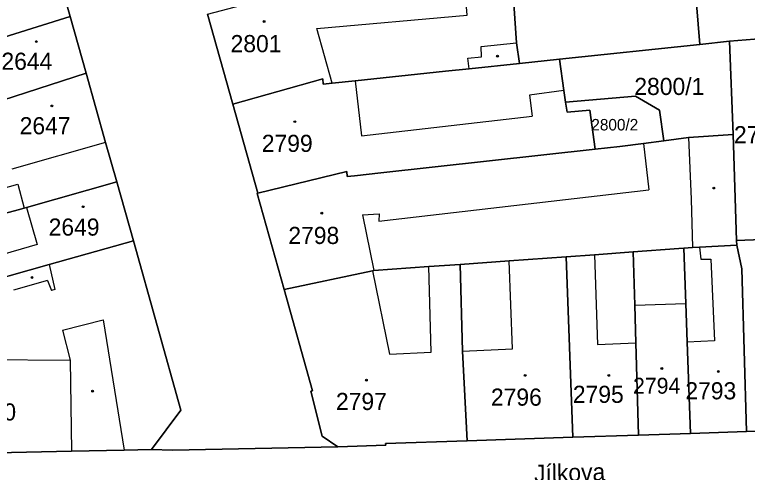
# Model space of a CAD drawing. Extents: x -596233 to -595156, y -1161235 to -1159375.
# Drawn here: x -595617.7 to -595544.9, y -1160883.5 to -1160838.1 of the extents above; entities that cross this region are included whole.
import ezdxf

# ---------------------------------------------------------------- set-up
doc = ezdxf.new("R2010")
doc.units = 0
for name, color, linetype in [('KN_CAR_KR', 7, 'Continuous'), ('KN_KULTURY', 7, 'Continuous'), ('KN_PARC_CIS_POZ', 7, 'Continuous'), ('KN_PARC_CIS_STAV', 7, 'Continuous'), ('KN_PARC_PLOCHA', 7, 'Continuous'), ('KN_ULICE', 7, 'Continuous'), ('parcely_l', 7, 'Continuous')]:
    doc.layers.add(name, color=color, linetype=linetype)

msp = doc.modelspace()

# ---------------------------------------------------------------- linework, layer by layer
at = {"layer": 'KN_CAR_KR'}
for points in [[(-595572.77, -1160838.12), (-595572.92, -1160836.45)], [(-595587.72, -1160839.46), (-595572.77, -1160838.12)], [(-595586.2, -1160844.88), (-595587.72, -1160839.46)], [(-595571.38, -1160841.24), (-595567.86, -1160840.88)], [(-595571.34, -1160842.27), (-595571.38, -1160841.24)], [(-595572.71, -1160842.42), (-595571.34, -1160842.27)], [(-595572.59, -1160843.45), (-595572.71, -1160842.42)], [(-595583.91, -1160844.64), (-595583.29, -1160850.11)], [(-595563.16, -1160845.63), (-595566.6, -1160846.09)], [(-595566.6, -1160846.09), (-595566.33, -1160848.16)], [(-595583.29, -1160850.11), (-595566.33, -1160848.16)], [(-595550.79, -1160850.29), (-595550.52, -1160856.41)], [(-595608.7, -1160850.76), (-595618.02, -1160853.42)], [(-595555.24, -1160850.87), (-595554.73, -1160855.47)], [(-595624.81, -1160856.96), (-595617.44, -1160854.91)], [(-595617.44, -1160854.91), (-595616.79, -1160857.29)], [(-595581.54, -1160858.57), (-595554.73, -1160855.47)], [(-595550.52, -1160856.41), (-595550.38, -1160861.19)], [(-595616.57, -1160857.22), (-595615.5, -1160860.91)], [(-595583.18, -1160857.96), (-595581.51, -1160857.87)], [(-595583.18, -1160857.96), (-595582.05, -1160863.48)], [(-595581.51, -1160857.87), (-595581.54, -1160858.57)], [(-595615.5, -1160860.91), (-595619.75, -1160862.14)], [(-595549.68, -1160861.15), (-595549.57, -1160862.36)], [(-595560.11, -1160861.92), (-595559.84, -1160870.83)], [(-595549.57, -1160862.36), (-595548.55, -1160862.34)], [(-595548.55, -1160862.34), (-595548.19, -1160870.45)], [(-595614.32, -1160862.9), (-595613.75, -1160865.37)], [(-595576.36, -1160871.58), (-595576.6, -1160863.09)], [(-595568.26, -1160871.25), (-595568.62, -1160862.52)], [(-595582.18, -1160863.51), (-595580.48, -1160871.77)], [(-595614.49, -1160864.47), (-595617.87, -1160865.43)], [(-595614.49, -1160864.47), (-595614.09, -1160865.47)], [(-595613.75, -1160865.37), (-595614.09, -1160865.47)], [(-595556.13, -1160866.93), (-595551.05, -1160866.76)], [(-595612.98, -1160869.39), (-595608.96, -1160868.37)], [(-595608.96, -1160868.37), (-595606.86, -1160881.31)], [(-595612.98, -1160869.39), (-595612.24, -1160872.38)], [(-595559.84, -1160870.83), (-595556.03, -1160870.66)], [(-595548.19, -1160870.45), (-595550.92, -1160870.59)], [(-595580.48, -1160871.77), (-595576.36, -1160871.58)], [(-595573.23, -1160871.48), (-595568.26, -1160871.25)], [(-595620.71, -1160872.33), (-595612.24, -1160872.38)], [(-595612.24, -1160872.38), (-595612.11, -1160881.42)]]:
    msp.add_lwpolyline(points, dxfattribs=at)
at = {"layer": 'KN_KULTURY'}
for centre, radius in [((-595592.96, -1160838.77), 0.09), ((-595592.96, -1160838.77), 0.0398), ((-595615.59, -1160840.76), 0.09), ((-595615.59, -1160840.76), 0.0398), ((-595569.77, -1160842.21), 0.09), ((-595569.77, -1160842.21), 0.0398), ((-595614.04, -1160847.15), 0.09), ((-595614.04, -1160847.15), 0.0398), ((-595589.9, -1160848.71), 0.09), ((-595589.9, -1160848.71), 0.0398), ((-595548.28, -1160855.3), 0.09), ((-595548.28, -1160855.3), 0.0398), ((-595610.93, -1160857.15), 0.09), ((-595610.93, -1160857.15), 0.0398), ((-595587.23, -1160857.79), 0.09), ((-595587.23, -1160857.79), 0.0398), ((-595616.02, -1160864.17), 0.09), ((-595616.02, -1160864.17), 0.0398), ((-595553.44, -1160873.21), 0.09), ((-595553.44, -1160873.21), 0.0398), ((-595567.02, -1160873.89), 0.09), ((-595567.02, -1160873.89), 0.0398), ((-595558.71, -1160873.89), 0.09), ((-595558.71, -1160873.89), 0.0398), ((-595547.82, -1160873.51), 0.09), ((-595547.82, -1160873.51), 0.0398), ((-595582.79, -1160874.37), 0.09), ((-595582.79, -1160874.37), 0.0398), ((-595610, -1160875.46), 0.09), ((-595610, -1160875.46), 0.0398)]:
    msp.add_circle(centre, radius, dxfattribs=at)
at = {"layer": 'KN_PARC_PLOCHA'}
for points in [[(-595516.7, -1160837.52), (-595520.65, -1160838.61), (-595532.3, -1160839.58), (-595534.35, -1160839.75), (-595540.07, -1160840.2), (-595546.72, -1160840.73), (-595549.67, -1160841.05), (-595550.5, -1160830.91), (-595521.89, -1160826.97), (-595520.91, -1160831.93), (-595518.32, -1160831.24)], [(-595549.67, -1160841.05), (-595563.61, -1160842.5), (-595567.57, -1160842.92), (-595567.86, -1160840.88), (-595568.41, -1160833.12), (-595562.92, -1160832.28), (-595552.81, -1160831.16), (-595550.5, -1160830.91)], [(-595612.24, -1160838.27), (-595623.79, -1160841.88), (-595624.03, -1160841.96), (-595629.09, -1160843.48), (-595629.71, -1160843.67), (-595630.92, -1160839.99), (-595631.49, -1160837.94), (-595629.38, -1160837.31), (-595625.46, -1160836.14), (-595613.83, -1160832.66)], [(-595567.57, -1160842.92), (-595572.59, -1160843.45), (-595574.94, -1160843.7), (-595583.91, -1160844.64), (-595586.2, -1160844.88), (-595587.08, -1160844.97), (-595587.13, -1160844.47), (-595596.07, -1160846.97), (-595598.59, -1160838.03), (-595589.75, -1160835.69), (-595589.61, -1160836.22), (-595588.64, -1160835.88), (-595578.3, -1160834.49), (-595577.15, -1160834.34), (-595571.41, -1160833.57), (-595571.18, -1160833.54), (-595570.01, -1160833.36), (-595568.41, -1160833.12), (-595567.86, -1160840.88)], [(-595610.65, -1160843.89), (-595623.77, -1160848.14), (-595625, -1160848.51), (-595625.85, -1160848.77), (-595627.17, -1160849.16), (-595627.36, -1160849.22), (-595630.55, -1160850.17), (-595631.95, -1160844.35), (-595629.71, -1160843.67), (-595629.09, -1160843.48), (-595624.03, -1160841.96), (-595623.79, -1160841.88), (-595612.24, -1160838.27)], [(-595539.53, -1160855.06), (-595539.31, -1160860.19), (-595543.5, -1160860.39), (-595546.01, -1160860.51), (-595546.35, -1160849.97), (-595546.72, -1160840.73), (-595540.07, -1160840.2)], [(-595546.35, -1160849.97), (-595550.79, -1160850.29), (-595553.23, -1160850.61), (-595553.67, -1160847.56), (-595556.04, -1160846.19), (-595562.99, -1160846.78), (-595563.16, -1160845.63), (-595563.61, -1160842.5), (-595549.67, -1160841.05), (-595546.72, -1160840.73)], [(-595562.99, -1160846.78), (-595562.85, -1160847.75), (-595560.58, -1160847.57), (-595560.05, -1160851.43), (-595581.35, -1160853.79), (-595583.98, -1160854.08), (-595584.69, -1160854.16), (-595584.74, -1160853.66), (-595593.57, -1160855.82), (-595596.07, -1160846.97), (-595587.13, -1160844.47), (-595587.08, -1160844.97), (-595586.2, -1160844.88), (-595583.91, -1160844.64), (-595574.94, -1160843.7), (-595572.59, -1160843.45), (-595567.57, -1160842.92), (-595563.61, -1160842.5), (-595563.16, -1160845.63)], [(-595607.59, -1160854.68), (-595616.57, -1160857.22), (-595616.79, -1160857.29), (-595617.4, -1160857.46), (-595621.64, -1160858.6), (-595624.18, -1160859.28), (-595624.81, -1160856.96), (-595625.16, -1160855.38), (-595623.41, -1160854.96), (-595624.58, -1160850.23), (-595626.66, -1160850.89), (-595627.17, -1160849.16), (-595625.85, -1160848.77), (-595625, -1160848.51), (-595623.77, -1160848.14), (-595610.65, -1160843.89), (-595608.7, -1160850.76)], [(-595553.23, -1160850.61), (-595555.24, -1160850.87), (-595557.62, -1160851.16), (-595560.05, -1160851.43), (-595560.58, -1160847.57), (-595562.85, -1160847.75), (-595562.99, -1160846.78), (-595556.04, -1160846.19), (-595553.67, -1160847.56)], [(-595546.01, -1160860.51), (-595545.99, -1160860.97), (-595549.68, -1160861.15), (-595550.38, -1160861.19), (-595551.24, -1160861.25), (-595551.74, -1160861.29), (-595556.27, -1160861.63), (-595560.11, -1160861.92), (-595562.95, -1160862.12), (-595568.62, -1160862.52), (-595573.47, -1160862.87), (-595576.6, -1160863.09), (-595582.05, -1160863.48), (-595582.18, -1160863.51), (-595590.97, -1160865.36), (-595593.63, -1160855.84), (-595593.57, -1160855.82), (-595584.74, -1160853.66), (-595584.69, -1160854.16), (-595583.98, -1160854.08), (-595581.35, -1160853.79), (-595560.05, -1160851.43), (-595557.62, -1160851.16), (-595555.24, -1160850.87), (-595553.23, -1160850.61), (-595550.79, -1160850.29), (-595546.35, -1160849.97)], [(-595605.93, -1160860.54), (-595614.32, -1160862.9), (-595618.29, -1160864.01), (-595619.24, -1160864.28), (-595621.46, -1160864.93), (-595622.55, -1160865.24), (-595623.13, -1160863.11), (-595623.49, -1160861.8), (-595624.18, -1160859.28), (-595621.64, -1160858.6), (-595617.4, -1160857.46), (-595616.79, -1160857.29), (-595616.57, -1160857.22), (-595607.59, -1160854.68)], [(-595624.18, -1160859.28), (-595623.49, -1160861.8), (-595623.13, -1160863.11), (-595622.55, -1160865.24), (-595621.46, -1160864.93), (-595619.24, -1160864.28), (-595618.29, -1160864.01), (-595614.32, -1160862.9), (-595605.93, -1160860.54), (-595601.23, -1160877.36), (-595604.16, -1160881.25), (-595606.86, -1160881.31), (-595612.11, -1160881.42), (-595625.58, -1160881.7), (-595626.69, -1160872.81), (-595627.61, -1160868.82), (-595628.13, -1160866.61), (-595628.69, -1160864.19), (-595629.7, -1160860.44), (-595630.67, -1160856.87), (-595625.16, -1160855.38), (-595624.81, -1160856.96)], [(-595539.1, -1160864.33), (-595538.89, -1160867.43), (-595538.73, -1160870.28), (-595538.39, -1160879.26), (-595545.01, -1160879.47), (-595545.48, -1160863.33), (-595545.99, -1160860.97), (-595546.01, -1160860.51), (-595543.5, -1160860.39), (-595539.31, -1160860.19)], [(-595555.74, -1160879.82), (-595562.27, -1160880.03), (-595562.95, -1160862.12), (-595560.11, -1160861.92), (-595556.27, -1160861.63), (-595556.13, -1160866.93), (-595556.03, -1160870.66)], [(-595550.6, -1160879.65), (-595555.74, -1160879.82), (-595556.03, -1160870.66), (-595556.13, -1160866.93), (-595556.27, -1160861.63), (-595551.74, -1160861.29), (-595551.24, -1160861.25), (-595551.05, -1160866.76), (-595550.92, -1160870.59)], [(-595545.01, -1160879.47), (-595550.6, -1160879.65), (-595550.92, -1160870.59), (-595551.05, -1160866.76), (-595551.24, -1160861.25), (-595550.38, -1160861.19), (-595549.68, -1160861.15), (-595545.99, -1160860.97), (-595545.48, -1160863.33)], [(-595562.27, -1160880.03), (-595572.77, -1160880.39), (-595573.23, -1160871.48), (-595573.47, -1160862.87), (-595568.62, -1160862.52), (-595562.95, -1160862.12)], [(-595572.77, -1160880.39), (-595580.88, -1160880.66), (-595580.87, -1160880.83), (-595585.64, -1160880.98), (-595587.17, -1160879.93), (-595588.31, -1160875.45), (-595588.15, -1160875.41), (-595590.97, -1160865.36), (-595582.18, -1160863.51), (-595582.05, -1160863.48), (-595576.6, -1160863.09), (-595573.47, -1160862.87), (-595573.23, -1160871.48)]]:
    msp.add_lwpolyline(points, close=True, dxfattribs=at)
for points in [[(-595598.59, -1160838.03), (-595596.07, -1160846.97), (-595593.57, -1160855.82), (-595593.63, -1160855.84), (-595590.97, -1160865.36), (-595588.15, -1160875.41), (-595588.31, -1160875.45), (-595587.17, -1160879.93), (-595585.64, -1160880.98), (-595602.06, -1160881.31), (-595604.16, -1160881.25), (-595601.23, -1160877.36), (-595605.93, -1160860.54), (-595607.59, -1160854.68), (-595608.7, -1160850.76), (-595610.65, -1160843.89), (-595612.24, -1160838.27), (-595613.83, -1160832.66)], [(-595625.58, -1160881.7), (-595612.11, -1160881.42), (-595606.86, -1160881.31), (-595604.16, -1160881.25), (-595602.06, -1160881.31), (-595585.64, -1160880.98), (-595580.87, -1160880.83), (-595580.88, -1160880.66), (-595572.77, -1160880.39), (-595562.27, -1160880.03), (-595555.74, -1160879.82), (-595550.6, -1160879.65), (-595545.01, -1160879.47), (-595538.39, -1160879.26), (-595529.54, -1160878.93), (-595522.54, -1160878.67), (-595517.24, -1160878.47), (-595511.98, -1160878.27), (-595506.67, -1160878.07)]]:
    msp.add_lwpolyline(points, dxfattribs=at)
at = {"layer": 'parcely_l'}
for points in [[(-595549.67, -1160841.05), (-595550.5, -1160830.91)], [(-595613.83, -1160832.66), (-595612.24, -1160838.27)], [(-595568.41, -1160833.12), (-595567.86, -1160840.88), (-595567.57, -1160842.92)], [(-595612.24, -1160838.27), (-595623.79, -1160841.88), (-595624.03, -1160841.96), (-595629.09, -1160843.48), (-595629.71, -1160843.67)], [(-595612.24, -1160838.27), (-595610.65, -1160843.89)], [(-595596.07, -1160846.97), (-595598.59, -1160838.03)], [(-595546.72, -1160840.73), (-595540.07, -1160840.2)], [(-595563.61, -1160842.5), (-595549.67, -1160841.05)], [(-595546.72, -1160840.73), (-595549.67, -1160841.05)], [(-595546.35, -1160849.97), (-595546.72, -1160840.73)], [(-595567.57, -1160842.92), (-595563.61, -1160842.5)], [(-595563.61, -1160842.5), (-595563.16, -1160845.63), (-595562.99, -1160846.78)], [(-595596.07, -1160846.97), (-595587.13, -1160844.47), (-595587.08, -1160844.97), (-595586.2, -1160844.88), (-595583.91, -1160844.64), (-595574.94, -1160843.7), (-595572.59, -1160843.45), (-595567.57, -1160842.92)], [(-595627.17, -1160849.16), (-595625.85, -1160848.77), (-595625, -1160848.51), (-595623.77, -1160848.14), (-595610.65, -1160843.89)], [(-595610.65, -1160843.89), (-595608.7, -1160850.76), (-595607.59, -1160854.68)], [(-595562.99, -1160846.78), (-595556.04, -1160846.19), (-595553.67, -1160847.56), (-595553.23, -1160850.61)], [(-595593.57, -1160855.82), (-595596.07, -1160846.97)], [(-595560.05, -1160851.43), (-595560.58, -1160847.57), (-595562.85, -1160847.75), (-595562.99, -1160846.78)], [(-595546.35, -1160849.97), (-595550.79, -1160850.29), (-595553.23, -1160850.61)], [(-595546.01, -1160860.51), (-595546.35, -1160849.97)], [(-595553.23, -1160850.61), (-595555.24, -1160850.87), (-595557.62, -1160851.16), (-595560.05, -1160851.43)], [(-595560.05, -1160851.43), (-595581.35, -1160853.79), (-595583.98, -1160854.08), (-595584.69, -1160854.16), (-595584.74, -1160853.66), (-595593.57, -1160855.82)], [(-595607.59, -1160854.68), (-595616.57, -1160857.22), (-595616.79, -1160857.29), (-595617.4, -1160857.46), (-595621.64, -1160858.6), (-595624.18, -1160859.28)], [(-595605.93, -1160860.54), (-595607.59, -1160854.68)], [(-595593.57, -1160855.82), (-595593.63, -1160855.84), (-595590.97, -1160865.36)], [(-595624.18, -1160859.28), (-595623.49, -1160861.8), (-595623.13, -1160863.11), (-595622.55, -1160865.24), (-595621.46, -1160864.93), (-595619.24, -1160864.28), (-595618.29, -1160864.01), (-595614.32, -1160862.9), (-595605.93, -1160860.54)], [(-595605.93, -1160860.54), (-595601.23, -1160877.36), (-595604.16, -1160881.25)], [(-595546.01, -1160860.51), (-595543.5, -1160860.39), (-595539.31, -1160860.19)], [(-595545.99, -1160860.97), (-595546.01, -1160860.51)], [(-595562.95, -1160862.12), (-595560.11, -1160861.92), (-595556.27, -1160861.63)], [(-595556.27, -1160861.63), (-595551.74, -1160861.29), (-595551.24, -1160861.25)], [(-595555.74, -1160879.82), (-595556.03, -1160870.66), (-595556.13, -1160866.93), (-595556.27, -1160861.63)], [(-595545.99, -1160860.97), (-595549.68, -1160861.15), (-595550.38, -1160861.19), (-595551.24, -1160861.25)], [(-595551.24, -1160861.25), (-595551.05, -1160866.76), (-595550.92, -1160870.59), (-595550.6, -1160879.65)], [(-595545.01, -1160879.47), (-595545.48, -1160863.33), (-595545.99, -1160860.97)], [(-595573.47, -1160862.87), (-595568.62, -1160862.52), (-595562.95, -1160862.12)], [(-595562.95, -1160862.12), (-595562.27, -1160880.03)], [(-595590.97, -1160865.36), (-595582.18, -1160863.51), (-595582.05, -1160863.48), (-595576.6, -1160863.09), (-595573.47, -1160862.87)], [(-595573.47, -1160862.87), (-595573.23, -1160871.48), (-595572.77, -1160880.39)], [(-595585.64, -1160880.98), (-595587.17, -1160879.93), (-595588.31, -1160875.45), (-595588.15, -1160875.41), (-595590.97, -1160865.36)], [(-595562.27, -1160880.03), (-595555.74, -1160879.82)], [(-595550.6, -1160879.65), (-595555.74, -1160879.82)], [(-595550.6, -1160879.65), (-595545.01, -1160879.47)], [(-595545.01, -1160879.47), (-595538.39, -1160879.26)], [(-595585.64, -1160880.98), (-595580.87, -1160880.83), (-595580.88, -1160880.66), (-595572.77, -1160880.39)], [(-595572.77, -1160880.39), (-595562.27, -1160880.03)], [(-595625.58, -1160881.7), (-595612.11, -1160881.42), (-595606.86, -1160881.31), (-595604.16, -1160881.25)], [(-595604.16, -1160881.25), (-595602.06, -1160881.31), (-595585.64, -1160880.98)]]:
    msp.add_lwpolyline(points, dxfattribs=at)

# ---------------------------------------------------------------- texts
at = {"layer": 'KN_PARC_CIS_POZ'}
for s, height, p in [('2800/1', 1.7, (-595556.1666, -1160846.06)), ('2800/2', 1.14, (-595560.44, -1160849.58))]:
    msp.add_text(s, height=height, dxfattribs=at).set_placement(p)
at = {"layer": 'KN_PARC_CIS_STAV'}
for s, height, p in [('2801', 1.7, (-595596.2866, -1160841.81)), ('2644', 1.7, (-595619.0566, -1160843.56)), ('2647', 1.7, (-595617.2466, -1160849.96)), ('2781', 1.7, (-595546.2666, -1160850.85)), ('2799', 1.7, (-595593.1866, -1160851.71)), ('2649', 1.7, (-595614.3666, -1160860.02)), ('2798', 1.7, (-595590.5466, -1160860.85)), ('2794', 1.58, (-595556.2966, -1160875.71)), ('2793', 1.7, (-595551.0966, -1160876.27)), ('2796', 1.7, (-595570.4166, -1160876.9)), ('2795', 1.7, (-595562.2766, -1160876.62)), ('2797', 1.7, (-595585.8166, -1160877.33)), ('2650', 1.7, (-595622.6566, -1160878.37))]:
    msp.add_text(s, height=height, dxfattribs=at).set_placement(p)
at = {"layer": 'KN_ULICE'}
msp.add_text('Jílkova', height=1.7, rotation=1.321294, dxfattribs=at).set_placement((-595566.1151, -1160884.4707))

doc.saveas('drawing.dxf')
